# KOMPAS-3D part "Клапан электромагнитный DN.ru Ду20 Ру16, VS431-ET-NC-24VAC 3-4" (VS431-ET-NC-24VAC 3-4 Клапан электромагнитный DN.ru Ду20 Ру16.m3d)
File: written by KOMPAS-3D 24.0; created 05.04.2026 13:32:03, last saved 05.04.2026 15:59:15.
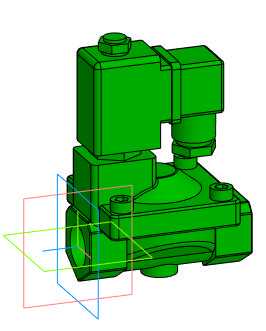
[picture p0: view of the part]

Document properties: Автор: artio; Полное имя файла: VS431-ET-NC-24VAC 3-4 Клапан электромагнитный DN.ru Ду20 Ру16.cdw

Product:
- Body: Тело 1  | qty 1
    Масса: 1.198355
- Part/product: Клапан электромагнитный DN.ru Ду20 Ру16  | designation VS431-ET-NC-24VAC 3-4
    Масса: 0.907
    Раздел спецификации: Прочие изделия
    Форматы листов документа: A3
    Примечание: D130-05503
    additional columns: ef56311e-7521-43dc-8291-0e6108b3d81d; artio; c; Шероховатость не задана; Да

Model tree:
1. Операция без истории:1

Expressions: VS431-ET-NC-24VAC 3-4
